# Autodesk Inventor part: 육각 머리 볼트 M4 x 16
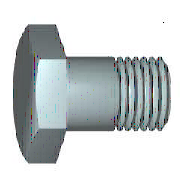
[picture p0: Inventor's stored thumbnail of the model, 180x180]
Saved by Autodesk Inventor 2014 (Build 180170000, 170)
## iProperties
IsCustomPart: 0
Created: 2012-02
Part Number: 육각 머리 볼트 M4 x 16
Material: 강철, 연강
Description: 6각 머리 볼트 및 6각 머리 나사
Document SubType Name: Modeling
Standard: KS B 1002
Designer: mduedu
Standards Organization: KS
Language: ko-KR
Size Designation: A + B M4 x 16
Categories: <MemberInstance><Categories><Category DisplayName="조임쇠" InternalName="e4da775c-781d-43d5-af7c-5136215cf5a6" Mnemonic="FSTN"><Category DisplayName="볼트" InternalN
Density: 7.86 g/cm^3
Appearance: 강철
Mass: 2.45486 g
Surface Area: 3.4613 cm^2
Volume: 0.312323 cm^3
Author: mduedu
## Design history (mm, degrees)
sketch "스케치1"
  geometry: L1 (0, 2.94)-(0, 2); L2 (2.1, 2)-(16, 2); L3 (16, 2)-(16, 0); L4 (16, 0)-(-0.4, 0); L5 (-3.68, 0)-(19.28, 0) reference; L6 (-0.4, 0)-(-0.4, 2.94); L7 (-0.4, 2.94)-(0, 2.94); L8 (2.1, 2)-(1.67, 2); L9 (1.67, 2)-(0, 2); L10 (0, -0.588)-(0, 3.528) reference
  constraints: 16 end point, 2 collinear, 2 perpendicular, 1 parallel
  dimensions: "d0" = 16 distance between parallel lines of L3 L1 (= NLG); "d1" = 13.9 distance from line of L2.start L3 (= GEL); "d2" = 4 diameter of L2 L4 (= GD); "d9" = 0.4001 distance between parallel lines of L6 L1 (computed from SD); "d10" = 5.88 diameter of L7 L4 (= SD2); "d13" = 0.42952 distance of L2.start L8.end (computed from GAL); "d14" = 4 diameter of L9 L4 (= BDM)
revolve "본체" sketch "스케치1" stored, may be unused: angle "d12" = 90 deg
sketch "스케치2"
  geometry: L1 (0, 4.041)-(3.5, 2.021); L2 (3.5, 2.021)-(3.5, -2.021); L3 (3.5, -2.021)-(0, -4.041); L4 (0, -4.041)-(-3.5, -2.021); L5 (-3.5, -2.021)-(-3.5, 2.021); L6 (-3.5, 2.021)-(0, 4.041); 2 further points
  constraints: 12 end point, 1 coincident, 1 vertical, 11 other
  dimensions: "d11" = 7 distance between parallel lines of L5 L2 (= SW)
extrude "머리" join sketch "스케치2" distance "d3" = 2.4 (= KOH - SD); taper "d4" = 0 deg
sketch "스케치4"
  geometry: L1 (-2.8, 3.5)-(-2.8, 4.041); L2 (-2.8, 4.041)-(-2.487, 4.041); L3 (-2.487, 4.041)-(-2.8, 3.5); L4 (-3.28, 0)-(0.08, 0) reference; L5 (-0.4, 4.041)-(-2.8, 4.041) reference; L6 (-2.8, 2.021)-(-2.8, 4.041) reference
  constraints: 6 end point, 2 collinear, 1 perpendicular, 1 vertical
  dimensions: "d5" = 30 deg angle of L3 L1 (= ANG1); "d19" = 7 diameter of L1.start L4 (= SW0)
revolve "모따기1" sketch "스케치4" stored, may be unused: angle "d21" = 90 deg
workplane "Work Plane1"
body "Solid1"
feature "스레드" dims "d15" = 13.9 (= GEL), "d16" = 0
chamfer "모따기2" distance "d6" = 0.42941 (= -0.5 x SPD + 0.5 x GD); stored, may be unused: second distance "d7" = 0.42952 (computed from GUL), angle "d55" = 45 deg
other parameters: "NLG" = 16 [user parameter; used in 1 equation term], "GD" = 4 (= NND) [user parameter; used in 2 equation terms], "BDM" = 4 (= NND) [user parameter; used in 1 equation term], "KOH" = 2.8 [user parameter; used in 1 equation term], "GEL" = 13.9 [user parameter; used in 2 equation terms], "SW" = 7 [user parameter; used in 3 equation terms], "SW0" = 7 (= SW) [user parameter; used in 1 equation term], "SPD" = 3.14117 (= NND - 1.2269 x PTC) [user parameter; used in 1 equation term], "SD2" = 5.88 (= SDH) [user parameter; used in 1 equation term], "SD" = 0.4 [user parameter; used in 2 equation terms], "ANG1" = 30 deg [user parameter; used in 1 equation term], "GAL" = 0.42941 (= 0.61345 x PTC) [user parameter; used in 1 equation term], "GUL" = 0.42941 (= 0.61345 x PTC) [user parameter; used in 1 equation term], "d8" = 0, "RR" = 0.2 [user parameter], "d57" = 0, "d58" = 0, "TPU" = 14.28571 (computed from PTC) [user parameter], "GD1" = 3.14117 (= THREADDIA - 1.2269 x PTC) [user parameter], "THREADDIA" = 4 [user parameter; used in 1 equation term], "SDH" = 5.88 [user parameter; used in 1 equation term], "SDHG" = 2.1 [user parameter], "TOA" = 30 deg [user parameter], "PTC" = 0.7 [user parameter; used in 5 equation terms], "NND" = 4 [user parameter; used in 3 equation terms], "E0" = 8.085 (= 1.155 x SW) [user parameter]
